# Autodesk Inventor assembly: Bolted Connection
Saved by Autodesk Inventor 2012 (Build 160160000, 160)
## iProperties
Created: 2010-12
Part Number: Bolted Connection
Document SubType Name: Assembly
Designer: Thom Tremblay
ClientObjectVersion: 1
Author: Thom Tremblay
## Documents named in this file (3)
- C:\Users\VMuser\Desktop\Inventor 2012 Essentials\Assemblies\Chapter 6\c6-01\Design Accelerator\Bolted Connection3.iam
- C:\Users\VMuser\Desktop\Inventor 2012 Essentials\Content Center Files\en-US\ISO 7089\ISO 7089 - 4 - 140 HV.ipt
- C:\Users\VMuser\Desktop\Inventor 2012 Essentials\Content Center Files\en-US\ISO 4762\ISO 4762 - M4 x 10ISO.ipt
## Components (16 placed, 2 different names)
1. ISO 4762 M4 x 10:1
2. ISO 7089 4 - 140 HV:1
3. ISO 4762 M4 x 10:2
4. ISO 4762 M4 x 10:3
5. ISO 4762 M4 x 10:4
6. ISO 4762 M4 x 10:5
7. ISO 4762 M4 x 10:6
8. ISO 4762 M4 x 10:7
9. ISO 4762 M4 x 10:8
10. ISO 7089 4 - 140 HV:2
11. ISO 7089 4 - 140 HV:3
12. ISO 7089 4 - 140 HV:4
13. ISO 7089 4 - 140 HV:5
14. ISO 7089 4 - 140 HV:6
15. ISO 7089 4 - 140 HV:7
16. ISO 7089 4 - 140 HV:8
